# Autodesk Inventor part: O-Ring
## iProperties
Shininess: 64.0
Length Units: 11269
Angle Units: 11279
Time Units: 11290
Mass Units: 11283
Length Display Precision: 3
Angle Display Precision: 2
Compacted: True
Part Number: O-Ring
Document SubType Name: Modeling
Created: 2004-05
Material: Standard
Designer: KWU_CAD
Manufacturer: Standard
Standards Organization: Custom
Density: 0.0
Volumn: 0.0
Area: 0.0
PropertySet Name: Model Information
Control State: 0
Master: False
Checked Out: False
Author: KWU_CAD
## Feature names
1. Drehung1 [Revolution]
